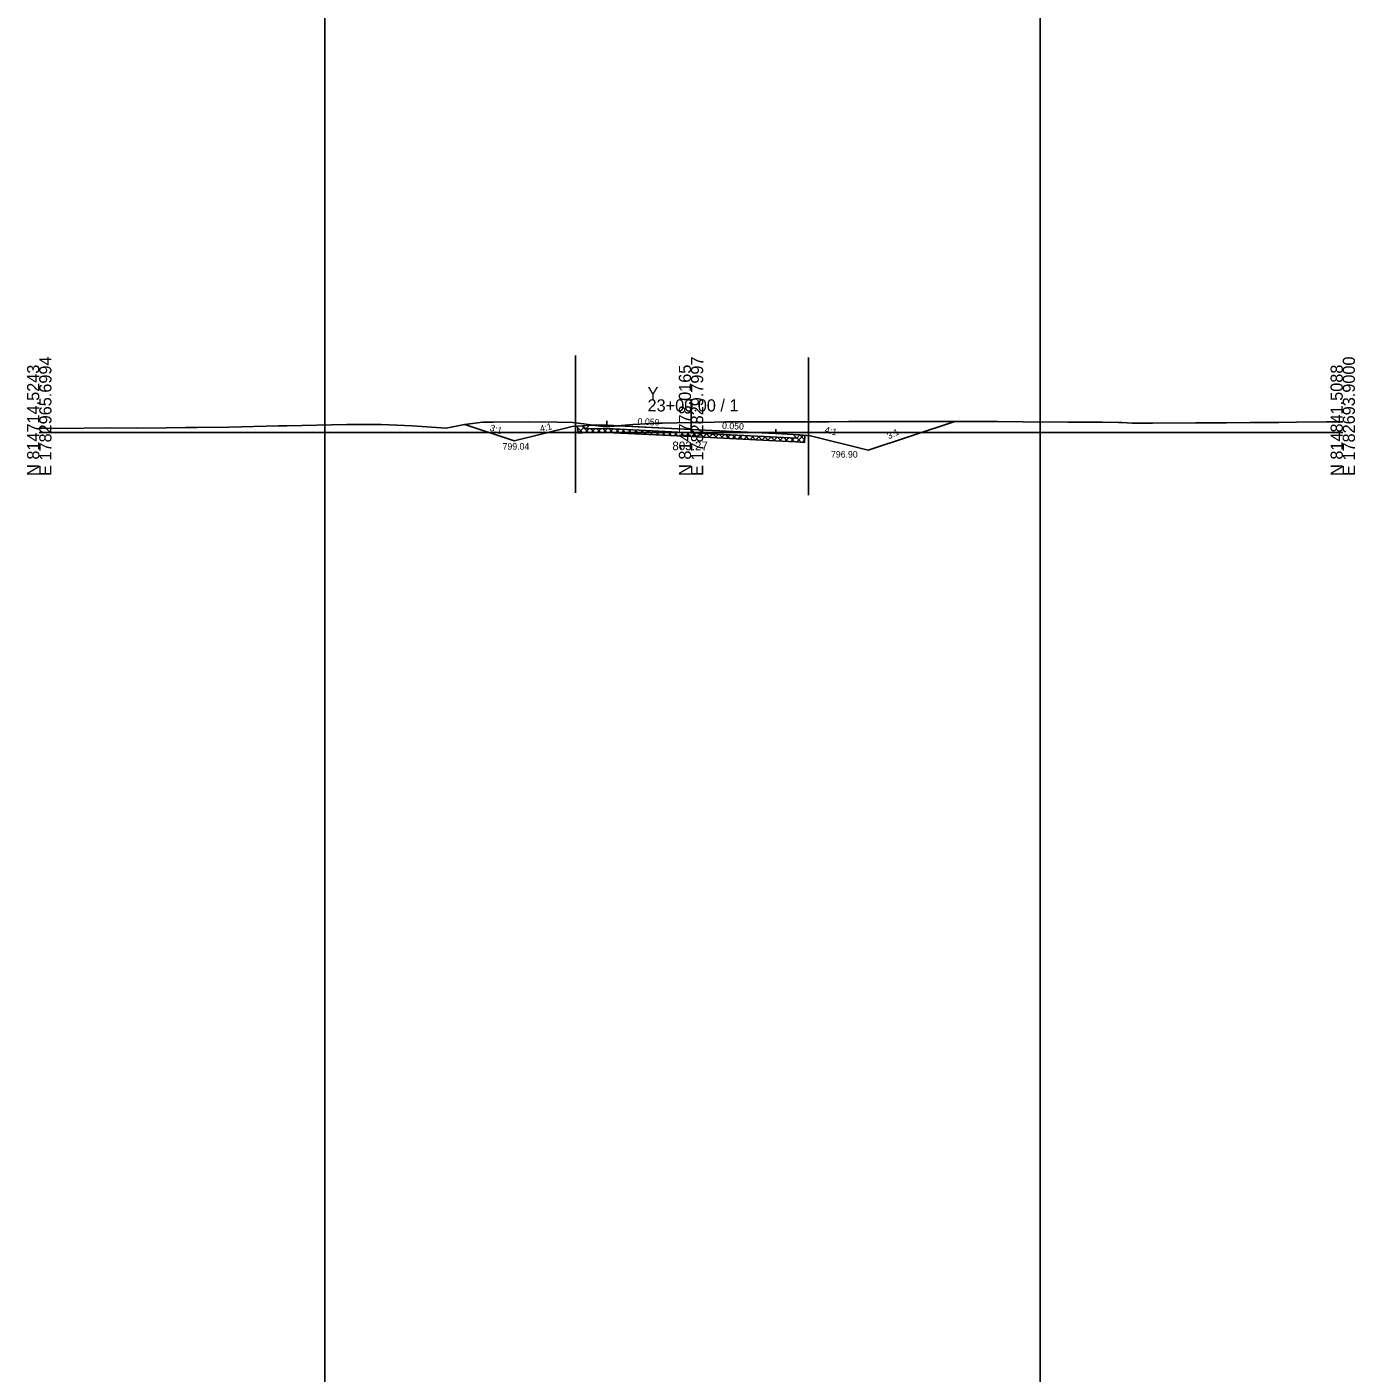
# Model space of a CAD drawing. Extents: x -12583 to 5303, y -44 to 25667.
# Drawn here: x 997.2 to 1302.8, y 3283.5 to 3593.4 of the extents above; entities that cross this region are included whole.
import ezdxf

# ---------------------------------------------------------------- set-up
doc = ezdxf.new("R2010")
doc.units = 0
for name, color, linetype in [('Exist Cross Section Cell', 7, 'Continuous'), ('Exist XS Center Line Elevation Label', 7, 'Continuous'), ('Exist XS Ground Line', 7, 'Continuous'), ('Prop CMT Shallow Undercut', 7, 'Continuous'), ('Prop XS Ditch Slope Text', 7, 'Continuous'), ('Prop XS Ditch Standard Text', 7, 'Continuous'), ('Prop XS Dump Level', 7, 'Continuous'), ('Prop XS Earthwork Shape', 7, 'Continuous'), ('Prop XS Earthwork Undercut', 7, 'Continuous'), ('Prop XS EOT Tick Mark', 7, 'Continuous'), ('Prop XS Exc Vertical Line 1', 7, 'Continuous'), ('Prop XS Exc Vertical Line 2', 7, 'Continuous'), ('Prop XS Finish Grade', 7, 'Continuous'), ('Prop XS Finish Grade Earthwork', 7, 'Continuous'), ('Prop XS Finish Grade Paved Shoulder', 7, 'Continuous'), ('Prop XS Finish Grade Pavement', 7, 'Continuous'), ('Prop XS Pvmt Edge Slope', 7, 'Continuous'), ('Prop XS SE Text', 7, 'Continuous'), ('Prop XS Side Slope Text', 7, 'Continuous'), ('Prop XS Subgrade Earthwork', 7, 'Continuous'), ('Prop XS Undercut Exc Hatch', 7, 'Continuous'), ('Scratch_Level_1', 7, 'Continuous'), ('Scratch_Level_2', 7, 'Continuous'), ('Scratch_Level_3', 7, 'Continuous'), ('Scratch_Level_6', 7, 'Continuous')]:
    doc.layers.add(name, color=color, linetype=linetype)

msp = doc.modelspace()

# ---------------------------------------------------------------- linework, layer by layer
at = {"layer": 'Exist Cross Section Cell'}
for p, q in [((1150, 3500), (1150, 3507.63)), ((1000, 3500), (1150, 3500)), ((1150, 3500), (1300, 3500))]:
    msp.add_line(p, q, dxfattribs=at)
at = {"layer": 'Exist XS Ground Line'}
for p, q in [((1056.94, 3501.52), (1070.68, 3501.84)), ((1070.68, 3501.84), (1073.61, 3501.85)), ((1073.61, 3501.85), (1078.74, 3501.83)), ((1078.74, 3501.83), (1085.82, 3501.53)), ((1095.95, 3501.48), (1097.88, 3501.82)), ((1097.88, 3501.82), (1099.74, 3502.1)), ((1099.74, 3502.1), (1102.01, 3502.38)), ((1102.01, 3502.38), (1104.53, 3502.39)), ((1104.53, 3502.39), (1112.51, 3502.41)), ((1112.51, 3502.41), (1119.22, 3502.35)), ((1119.22, 3502.35), (1122.8, 3502.33)), ((1122.8, 3502.33), (1123.97, 3502.15)), ((1123.97, 3502.15), (1125.32, 3501.98)), ((1125.32, 3501.98), (1126.3, 3501.82)), ((1126.3, 3501.82), (1130.29, 3501.3)), ((1130.29, 3501.3), (1136.62, 3501.82)), ((1136.62, 3501.82), (1138.25, 3501.93)), ((1138.25, 3501.93), (1140.49, 3502.07)), ((1140.49, 3502.07), (1142.01, 3502.14)), ((1142.01, 3502.14), (1143.47, 3502.17)), ((1143.47, 3502.17), (1150, 3502.27)), ((1150, 3502.27), (1152.73, 3502.31)), ((1152.73, 3502.31), (1155.35, 3502.39)), ((1155.35, 3502.39), (1157.96, 3502.42)), ((1157.96, 3502.42), (1160, 3502.42)), ((1160, 3502.42), (1169.76, 3502.43)), ((1169.76, 3502.43), (1170.84, 3502.42)), ((1170.84, 3502.42), (1181.73, 3502.46)), ((1181.73, 3502.46), (1186.29, 3502.5)), ((1186.29, 3502.5), (1200.22, 3502.51)), ((1200.22, 3502.51), (1203.73, 3502.53)), ((1203.73, 3502.53), (1204.84, 3502.53)), ((1204.84, 3502.53), (1207.09, 3502.54)), ((1207.09, 3502.54), (1220.56, 3502.53)), ((1220.56, 3502.53), (1226.45, 3502.48)), ((1226.45, 3502.48), (1236.82, 3502.4)), ((1236.82, 3502.4), (1244.68, 3502.36)), ((1244.68, 3502.36), (1248.4, 3502.33)), ((1248.4, 3502.33), (1249.24, 3502.27)), ((1249.24, 3502.27), (1251.5, 3502.13)), ((1251.5, 3502.13), (1256.22, 3502.11)), ((1256.22, 3502.11), (1266.1, 3502.22)), ((1266.1, 3502.22), (1272.73, 3502.22)), ((1272.73, 3502.22), (1273.23, 3502.25)), ((1273.23, 3502.25), (1278.71, 3502.29)), ((1278.71, 3502.29), (1285.31, 3502.33)), ((1285.31, 3502.33), (1289.39, 3502.37)), ((1289.39, 3502.37), (1296.25, 3502.44)), ((1296.25, 3502.44), (1296.87, 3502.44)), ((1296.87, 3502.44), (1297.87, 3502.44)), ((1297.87, 3502.44), (1298.85, 3502.45)), ((1298.85, 3502.45), (1300, 3502.45)), ((1000, 3501), (1001.19, 3500.99)), ((1001.19, 3500.99), (1005.04, 3500.93)), ((1005.04, 3500.93), (1015.52, 3501.08)), ((1015.52, 3501.08), (1022.36, 3501)), ((1022.36, 3501), (1029.23, 3501.07)), ((1029.23, 3501.07), (1033.76, 3501.14)), ((1033.76, 3501.14), (1036.34, 3501.17)), ((1036.34, 3501.17), (1043.64, 3501.22)), ((1043.64, 3501.22), (1055.06, 3501.49)), ((1055.06, 3501.49), (1056.27, 3501.5)), ((1056.27, 3501.5), (1056.94, 3501.52)), ((1085.82, 3501.53), (1093.62, 3500.96)), ((1093.62, 3500.96), (1095.95, 3501.48))]:
    msp.add_line(p, q, dxfattribs=at)
at = {"layer": 'Prop CMT Shallow Undercut'}
msp.add_lwpolyline([(1130.6, 3500.89), (1149.96, 3499.93), (1174.32, 3498.71), (1175.03, 3499.42), (1176.23, 3499.32), (1176.1, 3497.68), (1174.12, 3497.84), (1169.44, 3498.08), (1149.95, 3499.05), (1130.6, 3500.02), (1125.98, 3499.97), (1124.02, 3499.84), (1123.9, 3501.46), (1125.12, 3501.54), (1125.82, 3500.85)], close=True, dxfattribs=at)
at = {"layer": 'Prop XS Dump Level'}
for p, q in [((1130.62, 3501.69), (1150, 3500.72)), ((1150, 3500.72), (1169.49, 3499.74))]:
    msp.add_line(p, q, dxfattribs=at)
at = {"layer": 'Prop XS Earthwork Shape'}
msp.add_lwpolyline([(1125.82, 3500.85), (1125.12, 3501.54), (1122.62, 3501.37), (1109.31, 3498.04), (1097.94, 3501.83), (1099.74, 3502.1), (1102.01, 3502.38), (1104.53, 3502.39), (1112.51, 3502.41), (1119.22, 3502.35), (1122.8, 3502.33), (1123.97, 3502.15), (1125.32, 3501.98), (1126.3, 3501.82), (1130.29, 3501.3), (1136.62, 3501.82), (1138.25, 3501.93), (1140.49, 3502.07), (1142.01, 3502.14), (1143.47, 3502.17), (1150, 3502.27), (1152.73, 3502.31), (1155.35, 3502.39), (1157.96, 3502.42), (1160, 3502.42), (1169.76, 3502.43), (1170.84, 3502.42), (1181.73, 3502.46), (1186.29, 3502.5), (1200.22, 3502.51), (1203.73, 3502.53), (1204.84, 3502.53), (1207.09, 3502.54), (1210.7, 3502.54), (1190.78, 3495.9), (1177.49, 3499.22), (1175.03, 3499.42), (1174.32, 3498.71), (1149.96, 3499.93), (1130.6, 3500.89)], close=True, dxfattribs=at)
at = {"layer": 'Prop XS Earthwork Undercut'}
for p, q in [((1123.9, 3501.46), (1124.02, 3499.84)), ((1124.02, 3499.84), (1125.98, 3499.97)), ((1125.82, 3500.85), (1125.12, 3501.54)), ((1130.6, 3500.89), (1125.82, 3500.85)), ((1125.98, 3499.97), (1130.6, 3500.02)), ((1149.96, 3499.93), (1130.6, 3500.89)), ((1130.6, 3500.02), (1149.95, 3499.05)), ((1149.95, 3499.05), (1169.44, 3498.08)), ((1174.32, 3498.71), (1149.96, 3499.93)), ((1175.03, 3499.42), (1174.32, 3498.71)), ((1176.1, 3497.68), (1176.23, 3499.32)), ((1169.44, 3498.08), (1174.12, 3497.84)), ((1174.12, 3497.84), (1176.1, 3497.68))]:
    msp.add_line(p, q, dxfattribs=at)
at = {"layer": 'Prop XS EOT Tick Mark'}
for p, q in [((1130.62, 3501.69), (1130.62, 3502.69)), ((1169.49, 3499.74), (1169.49, 3500.74))]:
    msp.add_line(p, q, dxfattribs=at)
at = {"layer": 'Prop XS Exc Vertical Line 1'}
msp.add_line((1123.38, 3486.09), (1123.38, 3517.75), dxfattribs=at)
at = {"layer": 'Prop XS Exc Vertical Line 2'}
msp.add_line((1177.04, 3485.57), (1177.04, 3517.23), dxfattribs=at)
at = {"layer": 'Prop XS Finish Grade'}
for p, q in [((1126.62, 3501.65), (1125.12, 3501.54)), ((1173.49, 3499.54), (1175.03, 3499.42))]:
    msp.add_line(p, q, dxfattribs=at)
at = {"layer": 'Prop XS Finish Grade Earthwork'}
for p, q in [((1109.31, 3498.04), (1097.94, 3501.83)), ((1190.78, 3495.9), (1210.7, 3502.54)), ((1122.62, 3501.37), (1109.31, 3498.04)), ((1122.62, 3501.37), (1125.12, 3501.54)), ((1175.03, 3499.42), (1177.49, 3499.22)), ((1177.49, 3499.22), (1190.78, 3495.9))]:
    msp.add_line(p, q, dxfattribs=at)
at = {"layer": 'Prop XS Finish Grade Paved Shoulder'}
for p, q in [((1130.62, 3501.69), (1126.62, 3501.65)), ((1169.49, 3499.74), (1173.49, 3499.54))]:
    msp.add_line(p, q, dxfattribs=at)
at = {"layer": 'Prop XS Finish Grade Pavement'}
for p, q in [((1130.62, 3501.69), (1150, 3500.72)), ((1150, 3500.72), (1169.49, 3499.74))]:
    msp.add_line(p, q, dxfattribs=at)
at = {"layer": 'Prop XS Pvmt Edge Slope'}
for p, q in [((1126.62, 3501.65), (1125.82, 3500.85)), ((1173.49, 3499.54), (1174.32, 3498.71))]:
    msp.add_line(p, q, dxfattribs=at)
at = {"layer": 'Prop XS Subgrade Earthwork'}
for p, q in [((1125.82, 3500.85), (1125.12, 3501.54)), ((1130.6, 3500.89), (1125.82, 3500.85)), ((1130.6, 3500.89), (1149.96, 3499.93)), ((1149.96, 3499.93), (1174.32, 3498.71)), ((1174.32, 3498.71), (1175.03, 3499.42))]:
    msp.add_line(p, q, dxfattribs=at)
at = {"layer": 'Prop XS Undercut Exc Hatch'}
for p, q in [((1123.9, 3501.46), (1124.02, 3499.84)), ((1125.07, 3499.91), (1123.93, 3501.05)), ((1125.98, 3499.97), (1124.02, 3499.84)), ((1124.04, 3499.84), (1125.43, 3501.23)), ((1126.42, 3499.98), (1124.87, 3501.52)), ((1125.56, 3499.94), (1126.47, 3500.85)), ((1130.6, 3500.02), (1125.98, 3499.97)), ((1127.82, 3499.99), (1126.95, 3500.86)), ((1127.02, 3499.98), (1127.9, 3500.87)), ((1129.22, 3500.01), (1128.35, 3500.87)), ((1128.44, 3500), (1129.33, 3500.88)), ((1130, 3500.64), (1129.75, 3500.89)), ((1129.87, 3500.01), (1130, 3500.14)), ((1130, 3500.14), (1130.75, 3500.89)), ((1130.62, 3500.02), (1130, 3500.64)), ((1149.95, 3499.05), (1130.6, 3500.02)), ((1132.11, 3499.94), (1131.19, 3500.86)), ((1131.26, 3499.99), (1132.09, 3500.82)), ((1132.61, 3499.92), (1133.44, 3500.75)), ((1133.6, 3499.87), (1132.68, 3500.79)), ((1133.95, 3499.85), (1134.79, 3500.68)), ((1135.09, 3499.79), (1134.16, 3500.72)), ((1135.3, 3499.78), (1136.14, 3500.62)), ((1136.57, 3499.72), (1135.65, 3500.64)), ((1136.65, 3499.72), (1137.48, 3500.55)), ((1138.06, 3499.65), (1137.14, 3500.57)), ((1138, 3499.65), (1138.83, 3500.48)), ((1139.55, 3499.57), (1138.63, 3500.49)), ((1139.34, 3499.58), (1140, 3500.24)), ((1140, 3500.24), (1140.18, 3500.42)), ((1141.04, 3499.5), (1140.12, 3500.42)), ((1140.69, 3499.51), (1141.52, 3500.35)), ((1142.53, 3499.42), (1141.61, 3500.34)), ((1142.04, 3499.45), (1142.87, 3500.28)), ((1144.02, 3499.35), (1143.1, 3500.27)), ((1143.38, 3499.38), (1144.22, 3500.21)), ((1145.51, 3499.27), (1144.59, 3500.19)), ((1144.73, 3499.31), (1145.56, 3500.15)), ((1147, 3499.2), (1146.07, 3500.12)), ((1146.08, 3499.25), (1146.91, 3500.08)), ((1147.42, 3499.18), (1148.26, 3500.01)), ((1148.48, 3499.12), (1147.56, 3500.05)), ((1148.77, 3499.11), (1149.6, 3499.94)), ((1149.97, 3499.05), (1149.05, 3499.97)), ((1169.44, 3498.08), (1149.95, 3499.05)), ((1150.12, 3499.04), (1150.95, 3499.88)), ((1151.44, 3499), (1150.54, 3499.9)), ((1151.46, 3498.98), (1151.44, 3499)), ((1151.46, 3498.98), (1151.49, 3499)), ((1151.49, 3499), (1152.3, 3499.81)), ((1152.85, 3499), (1152.03, 3499.82)), ((1152.81, 3498.91), (1152.9, 3499)), ((1152.95, 3498.9), (1152.85, 3499)), ((1152.9, 3499), (1153.64, 3499.74)), ((1154.27, 3499), (1153.52, 3499.75)), ((1154.16, 3498.84), (1154.32, 3499)), ((1154.44, 3498.83), (1154.27, 3499)), ((1154.32, 3499), (1154.99, 3499.67)), ((1155.68, 3499), (1155.01, 3499.67)), ((1155.5, 3498.77), (1155.73, 3499)), ((1155.93, 3498.75), (1155.68, 3499)), ((1155.73, 3499), (1156.34, 3499.61)), ((1157.09, 3499), (1156.49, 3499.6)), ((1156.85, 3498.71), (1157.15, 3499)), ((1157.42, 3498.68), (1157.09, 3499)), ((1157.15, 3499), (1157.69, 3499.54)), ((1158.51, 3499), (1157.98, 3499.53)), ((1158.2, 3498.64), (1158.56, 3499)), ((1158.9, 3498.6), (1158.51, 3499)), ((1158.56, 3499), (1159.03, 3499.47)), ((1159.92, 3499), (1159.47, 3499.45)), ((1159.55, 3498.57), (1159.97, 3499)), ((1160, 3498.92), (1159.92, 3499)), ((1159.97, 3499), (1160, 3499.03)), ((1160, 3499.03), (1160.38, 3499.41)), ((1160.39, 3498.53), (1160, 3498.92)), ((1160.89, 3498.5), (1161.39, 3499)), ((1161.34, 3499), (1160.96, 3499.38)), ((1161.88, 3498.45), (1161.34, 3499)), ((1161.39, 3499), (1161.73, 3499.34)), ((1162.24, 3498.44), (1162.8, 3499)), ((1162.75, 3499), (1162.45, 3499.3)), ((1163.37, 3498.38), (1162.75, 3499)), ((1162.8, 3499), (1163.07, 3499.27)), ((1163.59, 3498.37), (1164.22, 3499)), ((1164.16, 3499), (1163.94, 3499.23)), ((1164.86, 3498.31), (1164.16, 3499)), ((1164.22, 3499), (1164.42, 3499.2)), ((1164.93, 3498.3), (1165.63, 3499)), ((1165.58, 3499), (1165.43, 3499.15)), ((1166.35, 3498.23), (1165.58, 3499)), ((1165.63, 3499), (1165.77, 3499.14)), ((1166.28, 3498.23), (1167.04, 3499)), ((1166.99, 3499), (1166.91, 3499.08)), ((1167.84, 3498.16), (1166.99, 3499)), ((1167.04, 3499), (1167.11, 3499.07)), ((1167.63, 3498.17), (1168.46, 3499)), ((1169.32, 3498.08), (1168.4, 3499)), ((1168.97, 3498.1), (1169.81, 3498.93)), ((1170.81, 3498.01), (1169.89, 3498.93)), ((1170.32, 3498.03), (1171.15, 3498.87)), ((1172.3, 3497.93), (1171.38, 3498.86)), ((1171.67, 3497.97), (1172.5, 3498.8)), ((1173.79, 3497.86), (1172.87, 3498.78)), ((1173.01, 3497.9), (1173.85, 3498.73)), ((1175.32, 3497.75), (1174.34, 3498.73)), ((1174.35, 3497.82), (1175.88, 3499.35)), ((1176.15, 3498.33), (1175.05, 3499.43)), ((1176.23, 3499.32), (1176.1, 3497.68)), ((1169.44, 3498.08), (1174.12, 3497.84)), ((1174.12, 3497.84), (1176.1, 3497.68)), ((1175.66, 3497.72), (1176.14, 3498.2))]:
    msp.add_line(p, q, dxfattribs=at)
at = {"layer": 'Scratch_Level_1'}
msp.add_line((1065.76, 8031.12), (1065.76, -44.39), dxfattribs=at)
at = {"layer": 'Scratch_Level_2'}
msp.add_line((1230.36, 8031.12), (1230.36, -44.39), dxfattribs=at)
at = {"layer": 'Scratch_Level_3'}
msp.add_lwpolyline([(1127.54, 3501.66), (1126.62, 3501.65), (1125.12, 3501.54), (1125.82, 3500.85), (1130.6, 3500.89), (1149.96, 3499.93), (1174.32, 3498.71), (1175.03, 3499.42), (1173.49, 3499.54), (1169.49, 3499.74), (1150, 3500.72), (1133.35, 3501.55), (1130.29, 3501.3)], close=True, dxfattribs=at)
at = {"layer": 'Scratch_Level_6'}
msp.add_lwpolyline([(1123.9, 3501.46), (1125.12, 3501.54), (1125.82, 3500.85), (1130.6, 3500.89), (1149.96, 3499.93), (1174.32, 3498.71), (1175.03, 3499.42), (1176.23, 3499.32), (1176.1, 3497.68), (1174.12, 3497.84), (1169.44, 3498.08), (1149.95, 3499.05), (1130.6, 3500.02), (1125.98, 3499.97), (1124.02, 3499.84)], close=True, dxfattribs=at)

# ---------------------------------------------------------------- texts
at = {"layer": 'Exist Cross Section Cell'}
for s, p in [('E 1782965.6994', (1002.8, 3490)), ('E 1782829.7997', (1152.8, 3490)), ('E 1782693.9000', (1302.8, 3490)), ('N 814714.5243', (1000, 3490)), ('N 814778.0165', (1150, 3490)), ('N 814841.5088', (1300, 3490))]:
    msp.add_text(s, height=2.8, rotation=90, dxfattribs=at).set_placement(p)
for s, p in [('Y', (1140, 3507.63)), ('23+00.00 / 1', (1140, 3504.83))]:
    msp.add_text(s, height=2.8, dxfattribs=at).set_placement(p)
at = {"layer": 'Exist XS Center Line Elevation Label'}
msp.add_text('803.27', height=2, dxfattribs=at).set_placement((1145.7, 3495.91))
at = {"layer": 'Prop XS Ditch Slope Text'}
for rotation, p in [(14.0362, (1115.41, 3500.08)), (345.9638, (1180.67, 3499.97))]:
    msp.add_text('4:1', height=1.5, rotation=rotation, dxfattribs=at).set_placement(p)
at = {"layer": 'Prop XS Ditch Standard Text'}
for s, p in [('799.04', (1106.64, 3496.04)), ('796.90', (1182.22, 3494.22))]:
    msp.add_text(s, height=1.5, dxfattribs=at).set_placement(p)
at = {"layer": 'Prop XS Dump Level'}
for p in [(1122.62, 3501.33), (1177.49, 3499.18)]:
    msp.add_text('Case2', height=0.04, dxfattribs=at).set_placement(p)
at = {"layer": 'Prop XS SE Text'}
for p in [(1137.69, 3501.83), (1157.12, 3500.86)]:
    msp.add_text('0.050', height=1.5, rotation=357.1376, dxfattribs=at).set_placement(p)
at = {"layer": 'Prop XS Side Slope Text'}
for rotation, p in [(341.5651, (1103.56, 3500.47)), (26.5651, (1195.55, 3498.39))]:
    msp.add_text('3:1', height=1.5, rotation=rotation, dxfattribs=at).set_placement(p)

doc.saveas('drawing.dxf')
